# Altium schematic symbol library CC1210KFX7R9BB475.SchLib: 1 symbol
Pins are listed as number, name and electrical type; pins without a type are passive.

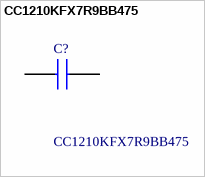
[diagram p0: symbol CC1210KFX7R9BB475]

## CC1210KFX7R9BB475
designator C?
Multilayer Ceramic Capacitors MLCC - SMD/SMT 50 V 4.7uF X7R 1210 10%; Manufacturer_Name: YAGEO; Geometry.Height: 2.8mm
footprint CAPC3225X280N
pins: 1, 2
